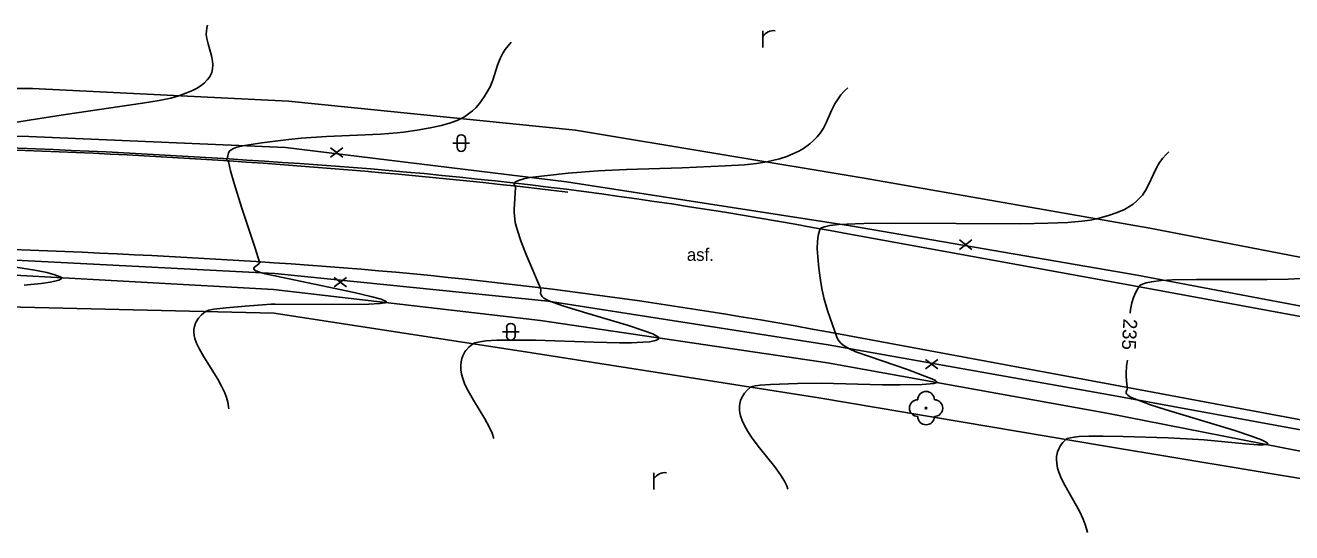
# Model space of a CAD drawing. Extents: x -593772 to -592667, y -1183541 to -1183371.
# Drawn here: x -593464.5 to -593388.6, y -1183406.9 to -1183376.6 of the extents above; entities that cross this region are included whole.
import ezdxf

# ---------------------------------------------------------------- set-up
doc = ezdxf.new("R2010")
doc.units = 0
for name, color, linetype in [('bez obruby', 7, 'Continuous'), ('hlavni vrstevnice', 7, 'Continuous'), ('popis ploch', 7, 'Continuous'), ('svisle dopravni znaceni', 7, 'Continuous'), ('terenni hrany', 7, 'Continuous'), ('vodorovne dopravni znaceni', 7, 'Continuous'), ('vrstevnice', 7, 'Continuous'), ('zelen', 7, 'Continuous')]:
    doc.layers.add(name, color=color, linetype=linetype)

msp = doc.modelspace()

# ---------------------------------------------------------------- linework, layer by layer
at = {"layer": 'bez obruby'}
for p, q in [((-593397.96, -1183392.17), (-593415.21, -1183389.05)), ((-593380.74, -1183395.34), (-593397.96, -1183392.17)), ((-593399.51, -1183398.03), (-593416.3, -1183394.93)), ((-593381.85, -1183401.35), (-593399.51, -1183398.03))]:
    msp.add_line(p, q, dxfattribs=at)
for centre, radius, start, end in [((-593480.94, -1183831.828), 448.192, 85.92367, 90.23652), ((-593466.139, -1183655.926), 271.692, 79.19585, 86.40007), ((-593484.14, -1183918.086), 528.447, 86.25017, 89.87092), ((-593468.055, -1183673.77), 283.602, 79.48509, 86.26488)]:
    msp.add_arc(centre, radius, start, end, dxfattribs=at)
at = {"layer": 'hlavni vrstevnice'}
for points in [[(-593386.907, -1183391.649), (-593388.835, -1183391.75), (-593390.089, -1183391.774), (-593394.334, -1183391.773), (-593395.785, -1183391.802), (-593396.442, -1183391.835), (-593397.025, -1183391.905), (-593397.35, -1183391.972), (-593397.57, -1183392.049), (-593397.698, -1183392.123), (-593397.787, -1183392.217), (-593397.968, -1183392.523), (-593398.106, -1183392.842), (-593398.205, -1183393.17), (-593398.281, -1183393.564), (-593398.302, -1183393.783)], [(-593398.468, -1183396.602), (-593398.514, -1183396.965), (-593398.542, -1183397.408), (-593398.542, -1183397.586), (-593398.507, -1183398.035), (-593398.466, -1183398.263), (-593398.469, -1183398.338), (-593398.536, -1183398.507), (-593398.538, -1183398.549), (-593398.512, -1183398.619), (-593398.44, -1183398.698), (-593398.272, -1183398.807), (-593397.928, -1183398.963), (-593397.078, -1183399.266), (-593396.212, -1183399.545), (-593392.04, -1183400.814), (-593391.043, -1183401.141), (-593390.428, -1183401.372), (-593390.2, -1183401.48), (-593390.104, -1183401.541), (-593390.061, -1183401.589), (-593390.069, -1183401.626), (-593390.125, -1183401.652), (-593390.331, -1183401.673), (-593390.653, -1183401.667), (-593391.388, -1183401.615), (-593393.871, -1183401.368), (-593394.205, -1183401.344), (-593396.02, -1183401.259), (-593398.723, -1183401.176), (-593399.926, -1183401.154), (-593400.774, -1183401.151), (-593401.359, -1183401.176), (-593401.64, -1183401.205), (-593401.9, -1183401.252), (-593402.046, -1183401.292), (-593402.159, -1183401.357), (-593402.334, -1183401.528), (-593402.476, -1183401.718), (-593402.578, -1183401.906), (-593402.649, -1183402.094), (-593402.675, -1183402.184), (-593402.707, -1183402.359), (-593402.717, -1183402.534), (-593402.699, -1183402.792), (-593402.645, -1183403.058), (-593402.568, -1183403.314), (-593402.427, -1183403.663), (-593402.216, -1183404.091), (-593401.34, -1183405.647), (-593401.111, -1183406.122), (-593400.99, -1183406.427), (-593400.908, -1183406.694), (-593400.857, -1183406.925)]]:
    msp.add_lwpolyline(points, dxfattribs=at)
at = {"layer": 'popis ploch'}
for p, q in [((-593420.3, -1183377.89), (-593420.3, -1183376.89)), ((-593438.6, -1183383.36), (-593438.6, -1183383.86)), ((-593438.1, -1183383.36), (-593438.1, -1183383.86)), ((-593438.85, -1183383.61), (-593437.85, -1183383.61)), ((-593435.63, -1183394.65), (-593435.63, -1183395.15)), ((-593435.13, -1183394.65), (-593435.13, -1183395.15)), ((-593435.88, -1183394.9), (-593434.88, -1183394.9)), ((-593426.81, -1183404.34), (-593426.81, -1183403.34))]:
    msp.add_line(p, q, dxfattribs=at)
for centre, radius, start, end in [((-593419.662, -1183377.627), 0.746, 81.32683, 148.70696), ((-593438.351, -1183383.36), 0.25, 0, 180), ((-593438.351, -1183383.86), 0.25, 180, 0), ((-593435.381, -1183394.65), 0.25, 0, 180), ((-593435.381, -1183395.15), 0.25, 180, 0), ((-593426.172, -1183404.078), 0.746, 81.32683, 148.70696)]:
    msp.add_arc(centre, radius, start, end, dxfattribs=at)
at = {"layer": 'svisle dopravni znaceni'}
for p, q in [((-593446.185, -1183384.451), (-593445.435, -1183383.889)), ((-593446.185, -1183383.889), (-593445.435, -1183384.451)), ((-593408.525, -1183389.971), (-593407.775, -1183389.409)), ((-593408.525, -1183389.409), (-593407.775, -1183389.971)), ((-593445.965, -1183392.211), (-593445.215, -1183391.649)), ((-593445.965, -1183391.649), (-593445.215, -1183392.211)), ((-593410.555, -1183397.121), (-593409.805, -1183396.559)), ((-593410.555, -1183396.559), (-593409.805, -1183397.121))]:
    msp.add_line(p, q, dxfattribs=at)
at = {"layer": 'terenni hrany'}
for p, q in [((-593464.02, -1183380.35), (-593482.62, -1183380.26)), ((-593448.69, -1183381.1), (-593464.02, -1183380.35)), ((-593431.5, -1183382.83), (-593448.69, -1183381.1)), ((-593464.25, -1183383.22), (-593482.66, -1183382.92)), ((-593448.88, -1183383.88), (-593464.25, -1183383.22)), ((-593414.23, -1183385.72), (-593431.5, -1183382.83)), ((-593432.05, -1183385.92), (-593448.88, -1183383.88)), ((-593415.05, -1183388.57), (-593432.05, -1183385.92)), ((-593397.13, -1183388.7), (-593414.23, -1183385.72)), ((-593397.88, -1183391.52), (-593415.05, -1183388.57)), ((-593379.66, -1183392.08), (-593397.13, -1183388.7)), ((-593449.51, -1183391.42), (-593465.42, -1183390.59)), ((-593449.59, -1183392.38), (-593465.44, -1183391.5)), ((-593433.14, -1183393.08), (-593449.51, -1183391.42)), ((-593380.46, -1183394.82), (-593397.88, -1183391.52)), ((-593433.6, -1183394.23), (-593449.59, -1183392.38)), ((-593416.39, -1183395.69), (-593433.14, -1183393.08)), ((-593449.56, -1183393.79), (-593465.57, -1183393.42)), ((-593434.13, -1183396.17), (-593449.56, -1183393.79)), ((-593416.42, -1183396.77), (-593433.6, -1183394.23)), ((-593416.93, -1183398.85), (-593434.13, -1183396.17)), ((-593399.53, -1183398.67), (-593416.39, -1183395.69)), ((-593399.69, -1183399.78), (-593416.42, -1183396.77)), ((-593399.9, -1183401.72), (-593416.93, -1183398.85)), ((-593382.12, -1183401.88), (-593399.53, -1183398.67)), ((-593382.43, -1183403.17), (-593399.69, -1183399.78)), ((-593382.81, -1183404.56), (-593399.9, -1183401.72))]:
    msp.add_line(p, q, dxfattribs=at)
at = {"layer": 'vodorovne dopravni znaceni'}
for centre, radius, start, end in [((-593483.843, -1184133.894), 750.085, 88.518486, 91.14869), ((-593478.399, -1183780.675), 396.861, 83.28158, 87.98577)]:
    msp.add_arc(centre, radius, start, end, dxfattribs=at)
at = {"layer": 'vrstevnice'}
for points in [[(-593453.535, -1183376.564), (-593453.587, -1183376.735), (-593453.61, -1183376.885), (-593453.613, -1183377.112), (-593453.584, -1183377.349), (-593453.51, -1183377.669), (-593453.3, -1183378.388), (-593453.238, -1183378.704), (-593453.22, -1183378.934), (-593453.236, -1183379.162), (-593453.291, -1183379.384), (-593453.386, -1183379.596), (-593453.427, -1183379.663), (-593453.554, -1183379.835), (-593453.717, -1183379.999), (-593453.931, -1183380.17), (-593454.205, -1183380.341), (-593454.443, -1183380.463), (-593454.833, -1183380.631), (-593455.259, -1183380.784), (-593455.733, -1183380.914), (-593456.431, -1183381.061), (-593457.426, -1183381.23), (-593462.046, -1183381.898), (-593464.222, -1183382.24), (-593466.072, -1183382.54)], [(-593435.356, -1183377.579), (-593435.545, -1183377.781), (-593435.721, -1183378.008), (-593435.864, -1183378.234), (-593436.02, -1183378.548), (-593436.172, -1183378.948), (-593436.462, -1183379.838), (-593436.627, -1183380.237), (-593436.792, -1183380.548), (-593436.986, -1183380.847), (-593437.262, -1183381.237), (-593437.482, -1183381.496), (-593437.684, -1183381.687), (-593437.906, -1183381.865), (-593438.16, -1183382.03), (-593438.357, -1183382.141), (-593438.593, -1183382.251), (-593438.995, -1183382.399), (-593439.529, -1183382.552), (-593440.201, -1183382.705), (-593440.99, -1183382.847), (-593441.81, -1183382.959), (-593442.192, -1183382.999), (-593443.183, -1183383.068), (-593446.416, -1183383.221), (-593447.941, -1183383.326), (-593448.859, -1183383.411), (-593450.298, -1183383.587), (-593451.324, -1183383.749), (-593451.777, -1183383.851), (-593451.991, -1183383.928), (-593452.132, -1183384.007), (-593452.226, -1183384.09), (-593452.288, -1183384.191), (-593452.373, -1183384.562), (-593452.392, -1183384.592), (-593452.421, -1183384.617), (-593452.292, -1183384.722), (-593452.172, -1183385.269), (-593451.955, -1183386.022), (-593451.494, -1183387.497), (-593450.68, -1183389.895), (-593450.436, -1183390.733), (-593450.435, -1183390.764), (-593450.458, -1183390.818), (-593450.563, -1183390.911), (-593450.724, -1183391.036), (-593450.766, -1183391.099), (-593450.767, -1183391.142), (-593450.729, -1183391.198), (-593450.644, -1183391.254), (-593450.435, -1183391.336), (-593450.084, -1183391.433), (-593449.505, -1183391.548), (-593444.765, -1183392.551), (-593443.676, -1183392.807), (-593443.146, -1183392.957), (-593442.919, -1183393.046), (-593442.855, -1183393.088), (-593442.843, -1183393.123), (-593442.88, -1183393.15), (-593442.927, -1183393.164), (-593443.216, -1183393.213), (-593443.876, -1183393.253), (-593444.958, -1183393.27), (-593449.488, -1183393.246), (-593449.737, -1183393.256), (-593451.283, -1183393.363), (-593452.432, -1183393.466), (-593453.162, -1183393.558), (-593453.458, -1183393.614), (-593453.619, -1183393.665), (-593453.665, -1183393.687), (-593453.896, -1183393.885), (-593454.085, -1183394.098), (-593454.216, -1183394.3), (-593454.262, -1183394.39), (-593454.33, -1183394.584), (-593454.362, -1183394.771), (-593454.363, -1183394.954), (-593454.339, -1183395.133), (-593454.293, -1183395.31), (-593454.193, -1183395.582), (-593454.018, -1183395.949), (-593453.764, -1183396.394), (-593452.923, -1183397.742), (-593452.678, -1183398.19), (-593452.507, -1183398.558), (-593452.402, -1183398.842), (-593452.324, -1183399.117), (-593452.279, -1183399.4), (-593452.268, -1183399.516)], [(-593415.199, -1183380.296), (-593415.424, -1183380.508), (-593415.622, -1183380.731), (-593415.785, -1183380.954), (-593415.974, -1183381.267), (-593416.172, -1183381.67), (-593416.5, -1183382.4), (-593416.669, -1183382.717), (-593416.869, -1183383.025), (-593417.045, -1183383.244), (-593417.253, -1183383.463), (-593417.482, -1183383.663), (-593417.85, -1183383.925), (-593418.137, -1183384.09), (-593418.496, -1183384.264), (-593418.861, -1183384.409), (-593419.287, -1183384.546), (-593420.06, -1183384.736), (-593420.678, -1183384.836), (-593421.399, -1183384.908), (-593422.546, -1183384.981), (-593425.114, -1183385.083), (-593428.461, -1183385.189), (-593430.159, -1183385.279), (-593431.94, -1183385.421), (-593434.235, -1183385.67), (-593434.607, -1183385.751), (-593434.921, -1183385.85), (-593435.096, -1183385.937), (-593435.168, -1183386.002), (-593435.19, -1183386.07), (-593435.187, -1183386.089), (-593435.104, -1183386.217), (-593435.096, -1183386.263), (-593435.173, -1183387.584), (-593435.174, -1183387.756), (-593435.15, -1183388.148), (-593435.118, -1183388.368), (-593435.008, -1183388.792), (-593434.764, -1183389.512), (-593434.417, -1183390.378), (-593433.599, -1183392.303), (-593433.589, -1183392.417), (-593433.599, -1183392.605), (-593433.574, -1183392.694), (-593433.512, -1183392.787), (-593433.399, -1183392.884), (-593433.137, -1183393.03), (-593432.836, -1183393.155), (-593432.213, -1183393.372), (-593430.84, -1183393.793), (-593428.34, -1183394.532), (-593427.396, -1183394.838), (-593426.881, -1183395.035), (-593426.633, -1183395.159), (-593426.557, -1183395.215), (-593426.522, -1183395.263), (-593426.52, -1183395.29), (-593426.559, -1183395.354), (-593426.654, -1183395.407), (-593426.797, -1183395.45), (-593427.078, -1183395.497), (-593427.469, -1183395.532), (-593428.153, -1183395.557), (-593428.884, -1183395.559), (-593430.409, -1183395.522), (-593433.899, -1183395.405), (-593435.584, -1183395.397), (-593436.222, -1183395.413), (-593436.884, -1183395.453), (-593437.235, -1183395.495), (-593437.538, -1183395.564), (-593437.661, -1183395.62), (-593437.896, -1183395.82), (-593438.072, -1183396.024), (-593438.134, -1183396.112), (-593438.253, -1183396.34), (-593438.313, -1183396.511), (-593438.354, -1183396.707), (-593438.373, -1183396.901), (-593438.367, -1183397.188), (-593438.331, -1183397.449), (-593438.261, -1183397.705), (-593438.131, -1183398.052), (-593437.944, -1183398.44), (-593437.625, -1183398.998), (-593436.936, -1183400.117), (-593436.675, -1183400.594), (-593436.503, -1183400.969), (-593436.389, -1183401.292)], [(-593395.98, -1183384.14), (-593396.172, -1183384.315), (-593396.35, -1183384.507), (-593396.543, -1183384.769), (-593396.705, -1183385.043), (-593396.907, -1183385.463), (-593397.196, -1183386.108), (-593397.384, -1183386.452), (-593397.566, -1183386.718), (-593397.733, -1183386.914), (-593397.914, -1183387.093), (-593398.123, -1183387.26), (-593398.378, -1183387.431), (-593398.643, -1183387.578), (-593399.086, -1183387.771), (-593399.596, -1183387.95), (-593400.231, -1183388.128), (-593400.669, -1183388.22), (-593401.19, -1183388.292), (-593402.03, -1183388.361), (-593403.226, -1183388.412), (-593404.846, -1183388.435), (-593412.592, -1183388.397), (-593414.253, -1183388.417), (-593415.269, -1183388.455), (-593415.756, -1183388.485), (-593416.276, -1183388.545), (-593416.61, -1183388.614), (-593416.788, -1183388.681), (-593416.865, -1183388.737), (-593416.889, -1183388.775), (-593416.974, -1183389.139), (-593417.021, -1183389.506), (-593417.034, -1183389.935), (-593417.009, -1183390.427), (-593416.932, -1183391.096), (-593416.811, -1183391.964), (-593416.737, -1183392.422), (-593416.616, -1183392.943), (-593416.412, -1183393.631), (-593415.84, -1183395.289), (-593415.747, -1183395.445), (-593415.606, -1183395.597), (-593415.417, -1183395.744), (-593415.104, -1183395.929), (-593414.719, -1183396.098), (-593413.916, -1183396.389), (-593411.636, -1183397.153), (-593411.01, -1183397.392), (-593410.182, -1183397.717), (-593409.962, -1183397.826), (-593409.9, -1183397.873), (-593409.881, -1183397.914), (-593409.894, -1183397.931), (-593409.939, -1183397.955), (-593410.062, -1183397.992), (-593410.271, -1183398.024), (-593410.758, -1183398.058), (-593412.068, -1183398.078), (-593413.125, -1183398.074), (-593416.791, -1183397.979), (-593418.22, -1183397.999), (-593419.837, -1183398.054), (-593420.452, -1183398.093), (-593420.744, -1183398.129), (-593420.918, -1183398.171), (-593421.027, -1183398.227), (-593421.231, -1183398.407), (-593421.389, -1183398.586), (-593421.449, -1183398.667), (-593421.554, -1183398.846), (-593421.627, -1183399.024), (-593421.671, -1183399.201), (-593421.693, -1183399.379), (-593421.69, -1183399.592), (-593421.673, -1183399.746), (-593421.63, -1183399.937), (-593421.535, -1183400.215), (-593421.399, -1183400.513), (-593421.191, -1183400.876), (-593420.93, -1183401.264), (-593420.486, -1183401.849), (-593419.577, -1183402.991), (-593419.238, -1183403.464), (-593419.003, -1183403.85), (-593418.865, -1183404.128), (-593418.787, -1183404.326)], [(-593465.406, -1183390.981), (-593463.876, -1183391.218), (-593463.171, -1183391.355), (-593462.753, -1183391.474), (-593462.295, -1183391.643), (-593462.268, -1183391.681), (-593462.304, -1183391.74), (-593462.436, -1183391.807), (-593462.689, -1183391.877), (-593462.953, -1183391.928), (-593463.501, -1183392.007), (-593464.526, -1183392.113)]]:
    msp.add_lwpolyline(points, dxfattribs=at)
at = {"layer": 'zelen'}
msp.add_circle((-593410.52, -1183399.47), 0.05, dxfattribs=at)
for centre, start, end in [((-593410.52, -1183398.97), 0, 180), ((-593411.02, -1183399.47), 90, 270), ((-593410.02, -1183399.47), 270, 90), ((-593410.52, -1183399.97), 180, 0)]:
    msp.add_arc(centre, 0.5, start, end, dxfattribs=at)

# ---------------------------------------------------------------- texts
at = {"layer": 'hlavni vrstevnice'}
msp.add_text('235', height=0.8351, rotation=266.90112, dxfattribs=at).set_placement((-593398.701, -1183394.105))
at = {"layer": 'popis ploch'}
msp.add_text('asf.', height=0.75, dxfattribs=at).set_placement((-593424.843, -1183390.66))

doc.saveas('drawing.dxf')
